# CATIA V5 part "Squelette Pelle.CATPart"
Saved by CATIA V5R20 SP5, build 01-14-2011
Part number: Squelette Pelle
Bounding box of the stored display mesh (mm): x -350 to -290, y -300 to -300, z -30 to 30
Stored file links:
  U:\CFAO\Thinkmotion\Squelette Pelle.CATPart
  U:\CFAO\Thinkmotion\Bras Articule.CATProduct
  U:\CFAO\Thinkmotion\Squelette Bielle 7.CATPart
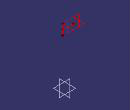
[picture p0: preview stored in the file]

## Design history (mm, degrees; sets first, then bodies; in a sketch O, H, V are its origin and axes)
Set1
  Line1: type PtPt, FirstPoint Point1, SecondPoint Point2
  Line2: type Normal, RefPoint Point2, RefSkin xy-plane, Start -30, End 30
  Plane1: type OffsetPt, RefPlane xy-plane, RefPoint Point1
  Plane2: type OffsetPt, RefPlane zx-plane, RefPoint Point1
Set2
  Point1: linked copy from another document
  Point2: linked copy from another document
Body1 (main body)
